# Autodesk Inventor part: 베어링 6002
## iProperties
Created: 2009-02
Part Number: 베어링 6002
Material: 강, 연강
Description: 깊은 그루브 볼 베어링
Document SubType Name: Modeling
Standard: KS B 2023
Designer: SeoGD™[esajin.kr]
Standards Organization: KS
Language: ko-KR
Size Designation: 6002 - 15 x 32 x 9
Categories: <MemberInstance><Categories><Category DisplayName="샤프트 부품" InternalName="7f7aeb1f-a693-4053-b835-cee3144e0d98" Mnemonic="SHFT"><Category DisplayName="베어링" Inter
Density: 1 g/cm^3
IsCustomPart: 1
Author: SeoGD™[esajin.kr]
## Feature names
1. IDS_ARRAYBALL[SIMPL:T] [Circular Pattern]
